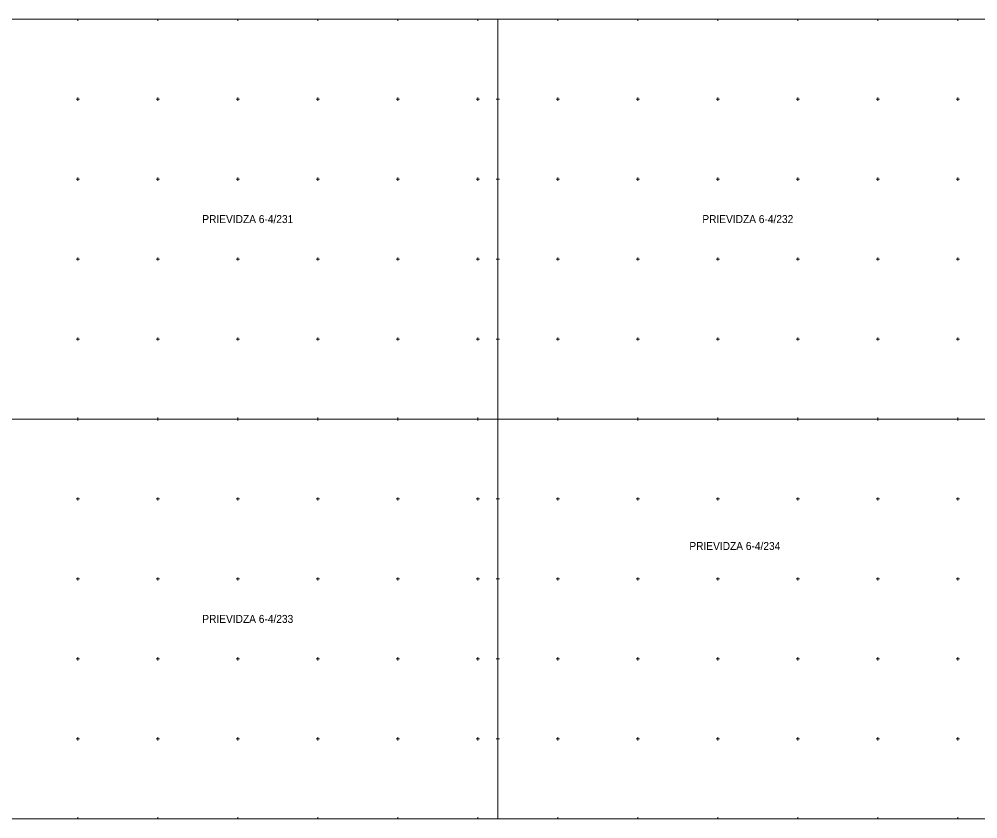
# Model space of a CAD drawing. Extents: x -46688 to -46438, y -123000 to -122825.
# Drawn here: x -46623.7 to -46563.8, y -122900 to -122850 of the extents above; entities that cross this region are included whole.
import ezdxf
from ezdxf.enums import TextEntityAlignment as Align

# ---------------------------------------------------------------- set-up
doc = ezdxf.new("R2010")
doc.units = 0
doc.header["$LTSCALE"] = 0.2
doc.layers.add('17', color=7, linetype='Continuous', lineweight=13)
doc.layers.add('18', color=7, linetype='Continuous', lineweight=13)
doc.layers.add('19', color=7, linetype='Continuous')

msp = doc.modelspace()

# ---------------------------------------------------------------- linework, layer by layer
at = {"layer": '17'}
for points in [[(-46593.75, -122850), (-46625, -122850), (-46625, -122875), (-46593.75, -122875)], [(-46562.5, -122850), (-46593.75, -122850), (-46593.75, -122875), (-46562.5, -122875)], [(-46593.75, -122875), (-46625, -122875), (-46625, -122900), (-46593.75, -122900)], [(-46562.5, -122875), (-46593.75, -122875), (-46593.75, -122900), (-46562.5, -122900)]]:
    msp.add_lwpolyline(points, close=True, dxfattribs=at)
at = {"layer": '18'}
for p, q in [((-46620, -122850), (-46620, -122850.1)), ((-46620, -122850), (-46620, -122850.1)), ((-46620, -122850), (-46620, -122850.1)), ((-46620, -122850), (-46620, -122850.1)), ((-46615, -122850), (-46615, -122850.1)), ((-46615, -122850), (-46615, -122850.1)), ((-46615, -122850), (-46615, -122850.1)), ((-46615, -122850), (-46615, -122850.1)), ((-46610, -122850), (-46610, -122850.1)), ((-46610, -122850), (-46610, -122850.1)), ((-46610, -122850), (-46610, -122850.1)), ((-46610, -122850), (-46610, -122850.1)), ((-46605, -122850), (-46605, -122850.1)), ((-46605, -122850), (-46605, -122850.1)), ((-46605, -122850), (-46605, -122850.1)), ((-46605, -122850), (-46605, -122850.1)), ((-46600, -122850), (-46600, -122850.1)), ((-46600, -122850), (-46600, -122850.1)), ((-46600, -122850), (-46600, -122850.1)), ((-46600, -122850), (-46600, -122850.1)), ((-46595, -122850), (-46595, -122850.1)), ((-46595, -122850), (-46595, -122850.1)), ((-46595, -122850), (-46595, -122850.1)), ((-46595, -122850), (-46595, -122850.1)), ((-46590, -122850), (-46590, -122850.1)), ((-46590, -122850), (-46590, -122850.1)), ((-46590, -122850), (-46590, -122850.1)), ((-46590, -122850), (-46590, -122850.1)), ((-46585, -122850), (-46585, -122850.1)), ((-46585, -122850), (-46585, -122850.1)), ((-46585, -122850), (-46585, -122850.1)), ((-46585, -122850), (-46585, -122850.1)), ((-46580, -122850), (-46580, -122850.1)), ((-46580, -122850), (-46580, -122850.1)), ((-46580, -122850), (-46580, -122850.1)), ((-46580, -122850), (-46580, -122850.1)), ((-46575, -122850), (-46575, -122850.1)), ((-46575, -122850), (-46575, -122850.1)), ((-46575, -122850), (-46575, -122850.1)), ((-46575, -122850), (-46575, -122850.1)), ((-46570, -122850), (-46570, -122850.1)), ((-46570, -122850), (-46570, -122850.1)), ((-46570, -122850), (-46570, -122850.1)), ((-46570, -122850), (-46570, -122850.1)), ((-46565, -122850), (-46565, -122850.1)), ((-46565, -122850), (-46565, -122850.1)), ((-46565, -122850), (-46565, -122850.1)), ((-46565, -122850), (-46565, -122850.1)), ((-46619.9, -122855), (-46620.1, -122855)), ((-46620, -122854.9), (-46620, -122855.1)), ((-46614.9, -122855), (-46615.1, -122855)), ((-46615, -122854.9), (-46615, -122855.1)), ((-46609.9, -122855), (-46610.1, -122855)), ((-46610, -122854.9), (-46610, -122855.1)), ((-46604.9, -122855), (-46605.1, -122855)), ((-46605, -122854.9), (-46605, -122855.1)), ((-46599.9, -122855), (-46600.1, -122855)), ((-46600, -122854.9), (-46600, -122855.1)), ((-46594.9, -122855), (-46595.1, -122855)), ((-46595, -122854.9), (-46595, -122855.1)), ((-46593.75, -122855), (-46593.85, -122855)), ((-46593.75, -122855), (-46593.65, -122855)), ((-46589.9, -122855), (-46590.1, -122855)), ((-46590, -122854.9), (-46590, -122855.1)), ((-46584.9, -122855), (-46585.1, -122855)), ((-46585, -122854.9), (-46585, -122855.1)), ((-46579.9, -122855), (-46580.1, -122855)), ((-46580, -122854.9), (-46580, -122855.1)), ((-46574.9, -122855), (-46575.1, -122855)), ((-46575, -122854.9), (-46575, -122855.1)), ((-46569.9, -122855), (-46570.1, -122855)), ((-46570, -122854.9), (-46570, -122855.1)), ((-46564.9, -122855), (-46565.1, -122855)), ((-46565, -122854.9), (-46565, -122855.1)), ((-46619.9, -122860), (-46620.1, -122860)), ((-46620, -122859.9), (-46620, -122860.1)), ((-46614.9, -122860), (-46615.1, -122860)), ((-46615, -122859.9), (-46615, -122860.1)), ((-46609.9, -122860), (-46610.1, -122860)), ((-46610, -122859.9), (-46610, -122860.1)), ((-46604.9, -122860), (-46605.1, -122860)), ((-46605, -122859.9), (-46605, -122860.1)), ((-46599.9, -122860), (-46600.1, -122860)), ((-46600, -122859.9), (-46600, -122860.1)), ((-46594.9, -122860), (-46595.1, -122860)), ((-46595, -122859.9), (-46595, -122860.1)), ((-46593.75, -122860), (-46593.85, -122860)), ((-46593.75, -122860), (-46593.65, -122860)), ((-46589.9, -122860), (-46590.1, -122860)), ((-46590, -122859.9), (-46590, -122860.1)), ((-46584.9, -122860), (-46585.1, -122860)), ((-46585, -122859.9), (-46585, -122860.1)), ((-46579.9, -122860), (-46580.1, -122860)), ((-46580, -122859.9), (-46580, -122860.1)), ((-46574.9, -122860), (-46575.1, -122860)), ((-46575, -122859.9), (-46575, -122860.1)), ((-46569.9, -122860), (-46570.1, -122860)), ((-46570, -122859.9), (-46570, -122860.1)), ((-46564.9, -122860), (-46565.1, -122860)), ((-46565, -122859.9), (-46565, -122860.1)), ((-46620, -122864.9), (-46620, -122865.1)), ((-46615, -122864.9), (-46615, -122865.1)), ((-46610, -122864.9), (-46610, -122865.1)), ((-46605, -122864.9), (-46605, -122865.1)), ((-46600, -122864.9), (-46600, -122865.1)), ((-46595, -122864.9), (-46595, -122865.1)), ((-46590, -122864.9), (-46590, -122865.1)), ((-46585, -122864.9), (-46585, -122865.1)), ((-46580, -122864.9), (-46580, -122865.1)), ((-46575, -122864.9), (-46575, -122865.1)), ((-46570, -122864.9), (-46570, -122865.1)), ((-46565, -122864.9), (-46565, -122865.1)), ((-46619.9, -122865), (-46620.1, -122865)), ((-46614.9, -122865), (-46615.1, -122865)), ((-46609.9, -122865), (-46610.1, -122865)), ((-46604.9, -122865), (-46605.1, -122865)), ((-46599.9, -122865), (-46600.1, -122865)), ((-46594.9, -122865), (-46595.1, -122865)), ((-46593.75, -122865), (-46593.85, -122865)), ((-46593.75, -122865), (-46593.65, -122865)), ((-46589.9, -122865), (-46590.1, -122865)), ((-46584.9, -122865), (-46585.1, -122865)), ((-46579.9, -122865), (-46580.1, -122865)), ((-46574.9, -122865), (-46575.1, -122865)), ((-46569.9, -122865), (-46570.1, -122865)), ((-46564.9, -122865), (-46565.1, -122865)), ((-46619.9, -122870), (-46620.1, -122870)), ((-46620, -122869.9), (-46620, -122870.1)), ((-46614.9, -122870), (-46615.1, -122870)), ((-46615, -122869.9), (-46615, -122870.1)), ((-46609.9, -122870), (-46610.1, -122870)), ((-46610, -122869.9), (-46610, -122870.1)), ((-46604.9, -122870), (-46605.1, -122870)), ((-46605, -122869.9), (-46605, -122870.1)), ((-46599.9, -122870), (-46600.1, -122870)), ((-46600, -122869.9), (-46600, -122870.1)), ((-46594.9, -122870), (-46595.1, -122870)), ((-46595, -122869.9), (-46595, -122870.1)), ((-46593.75, -122870), (-46593.85, -122870)), ((-46593.75, -122870), (-46593.65, -122870)), ((-46589.9, -122870), (-46590.1, -122870)), ((-46590, -122869.9), (-46590, -122870.1)), ((-46584.9, -122870), (-46585.1, -122870)), ((-46585, -122869.9), (-46585, -122870.1)), ((-46579.9, -122870), (-46580.1, -122870)), ((-46580, -122869.9), (-46580, -122870.1)), ((-46574.9, -122870), (-46575.1, -122870)), ((-46575, -122869.9), (-46575, -122870.1)), ((-46569.9, -122870), (-46570.1, -122870)), ((-46570, -122869.9), (-46570, -122870.1)), ((-46564.9, -122870), (-46565.1, -122870)), ((-46565, -122869.9), (-46565, -122870.1)), ((-46620, -122875), (-46620, -122874.9)), ((-46620, -122875), (-46620, -122874.9)), ((-46620, -122875), (-46620, -122874.9)), ((-46620, -122875), (-46620, -122874.9)), ((-46620, -122875), (-46620, -122875.1)), ((-46620, -122875), (-46620, -122875.1)), ((-46620, -122875), (-46620, -122875.1)), ((-46620, -122875), (-46620, -122875.1)), ((-46615, -122875), (-46615, -122874.9)), ((-46615, -122875), (-46615, -122874.9)), ((-46615, -122875), (-46615, -122874.9)), ((-46615, -122875), (-46615, -122874.9)), ((-46615, -122875), (-46615, -122875.1)), ((-46615, -122875), (-46615, -122875.1)), ((-46615, -122875), (-46615, -122875.1)), ((-46615, -122875), (-46615, -122875.1)), ((-46610, -122875), (-46610, -122874.9)), ((-46610, -122875), (-46610, -122874.9)), ((-46610, -122875), (-46610, -122874.9)), ((-46610, -122875), (-46610, -122874.9)), ((-46610, -122875), (-46610, -122875.1)), ((-46610, -122875), (-46610, -122875.1)), ((-46610, -122875), (-46610, -122875.1)), ((-46610, -122875), (-46610, -122875.1)), ((-46605, -122875), (-46605, -122874.9)), ((-46605, -122875), (-46605, -122874.9)), ((-46605, -122875), (-46605, -122874.9)), ((-46605, -122875), (-46605, -122874.9)), ((-46605, -122875), (-46605, -122875.1)), ((-46605, -122875), (-46605, -122875.1)), ((-46605, -122875), (-46605, -122875.1)), ((-46605, -122875), (-46605, -122875.1)), ((-46600, -122875), (-46600, -122874.9)), ((-46600, -122875), (-46600, -122874.9)), ((-46600, -122875), (-46600, -122874.9)), ((-46600, -122875), (-46600, -122874.9)), ((-46600, -122875), (-46600, -122875.1)), ((-46600, -122875), (-46600, -122875.1)), ((-46600, -122875), (-46600, -122875.1)), ((-46600, -122875), (-46600, -122875.1)), ((-46595, -122875), (-46595, -122874.9)), ((-46595, -122875), (-46595, -122874.9)), ((-46595, -122875), (-46595, -122874.9)), ((-46595, -122875), (-46595, -122874.9)), ((-46595, -122875), (-46595, -122875.1)), ((-46595, -122875), (-46595, -122875.1)), ((-46595, -122875), (-46595, -122875.1)), ((-46595, -122875), (-46595, -122875.1)), ((-46590, -122875), (-46590, -122874.9)), ((-46590, -122875), (-46590, -122874.9)), ((-46590, -122875), (-46590, -122874.9)), ((-46590, -122875), (-46590, -122874.9)), ((-46590, -122875), (-46590, -122875.1)), ((-46590, -122875), (-46590, -122875.1)), ((-46590, -122875), (-46590, -122875.1)), ((-46590, -122875), (-46590, -122875.1)), ((-46585, -122875), (-46585, -122874.9)), ((-46585, -122875), (-46585, -122874.9)), ((-46585, -122875), (-46585, -122874.9)), ((-46585, -122875), (-46585, -122874.9)), ((-46585, -122875), (-46585, -122875.1)), ((-46585, -122875), (-46585, -122875.1)), ((-46585, -122875), (-46585, -122875.1)), ((-46585, -122875), (-46585, -122875.1)), ((-46580, -122875), (-46580, -122874.9)), ((-46580, -122875), (-46580, -122874.9)), ((-46580, -122875), (-46580, -122874.9)), ((-46580, -122875), (-46580, -122874.9)), ((-46580, -122875), (-46580, -122875.1)), ((-46580, -122875), (-46580, -122875.1)), ((-46580, -122875), (-46580, -122875.1)), ((-46580, -122875), (-46580, -122875.1)), ((-46575, -122875), (-46575, -122874.9)), ((-46575, -122875), (-46575, -122874.9)), ((-46575, -122875), (-46575, -122874.9)), ((-46575, -122875), (-46575, -122874.9)), ((-46575, -122875), (-46575, -122875.1)), ((-46575, -122875), (-46575, -122875.1)), ((-46575, -122875), (-46575, -122875.1)), ((-46575, -122875), (-46575, -122875.1)), ((-46570, -122875), (-46570, -122874.9)), ((-46570, -122875), (-46570, -122874.9)), ((-46570, -122875), (-46570, -122874.9)), ((-46570, -122875), (-46570, -122874.9)), ((-46570, -122875), (-46570, -122875.1)), ((-46570, -122875), (-46570, -122875.1)), ((-46570, -122875), (-46570, -122875.1)), ((-46570, -122875), (-46570, -122875.1)), ((-46565, -122875), (-46565, -122874.9)), ((-46565, -122875), (-46565, -122874.9)), ((-46565, -122875), (-46565, -122874.9)), ((-46565, -122875), (-46565, -122874.9)), ((-46565, -122875), (-46565, -122875.1)), ((-46565, -122875), (-46565, -122875.1)), ((-46565, -122875), (-46565, -122875.1)), ((-46565, -122875), (-46565, -122875.1)), ((-46620, -122879.9), (-46620, -122880.1)), ((-46615, -122879.9), (-46615, -122880.1)), ((-46610, -122879.9), (-46610, -122880.1)), ((-46605, -122879.9), (-46605, -122880.1)), ((-46600, -122879.9), (-46600, -122880.1)), ((-46595, -122879.9), (-46595, -122880.1)), ((-46590, -122879.9), (-46590, -122880.1)), ((-46585, -122879.9), (-46585, -122880.1)), ((-46580, -122879.9), (-46580, -122880.1)), ((-46575, -122879.9), (-46575, -122880.1)), ((-46570, -122879.9), (-46570, -122880.1)), ((-46565, -122879.9), (-46565, -122880.1)), ((-46619.9, -122880), (-46620.1, -122880)), ((-46614.9, -122880), (-46615.1, -122880)), ((-46609.9, -122880), (-46610.1, -122880)), ((-46604.9, -122880), (-46605.1, -122880)), ((-46599.9, -122880), (-46600.1, -122880)), ((-46594.9, -122880), (-46595.1, -122880)), ((-46593.75, -122880), (-46593.85, -122880)), ((-46593.75, -122880), (-46593.65, -122880)), ((-46589.9, -122880), (-46590.1, -122880)), ((-46584.9, -122880), (-46585.1, -122880)), ((-46579.9, -122880), (-46580.1, -122880)), ((-46574.9, -122880), (-46575.1, -122880)), ((-46569.9, -122880), (-46570.1, -122880)), ((-46564.9, -122880), (-46565.1, -122880)), ((-46619.9, -122885), (-46620.1, -122885)), ((-46620, -122884.9), (-46620, -122885.1)), ((-46614.9, -122885), (-46615.1, -122885)), ((-46615, -122884.9), (-46615, -122885.1)), ((-46609.9, -122885), (-46610.1, -122885)), ((-46610, -122884.9), (-46610, -122885.1)), ((-46604.9, -122885), (-46605.1, -122885)), ((-46605, -122884.9), (-46605, -122885.1)), ((-46599.9, -122885), (-46600.1, -122885)), ((-46600, -122884.9), (-46600, -122885.1)), ((-46594.9, -122885), (-46595.1, -122885)), ((-46595, -122884.9), (-46595, -122885.1)), ((-46593.75, -122885), (-46593.85, -122885)), ((-46593.75, -122885), (-46593.65, -122885)), ((-46589.9, -122885), (-46590.1, -122885)), ((-46590, -122884.9), (-46590, -122885.1)), ((-46584.9, -122885), (-46585.1, -122885)), ((-46585, -122884.9), (-46585, -122885.1)), ((-46579.9, -122885), (-46580.1, -122885)), ((-46580, -122884.9), (-46580, -122885.1)), ((-46574.9, -122885), (-46575.1, -122885)), ((-46575, -122884.9), (-46575, -122885.1)), ((-46569.9, -122885), (-46570.1, -122885)), ((-46570, -122884.9), (-46570, -122885.1)), ((-46564.9, -122885), (-46565.1, -122885)), ((-46565, -122884.9), (-46565, -122885.1)), ((-46619.9, -122890), (-46620.1, -122890)), ((-46620, -122889.9), (-46620, -122890.1)), ((-46614.9, -122890), (-46615.1, -122890)), ((-46615, -122889.9), (-46615, -122890.1)), ((-46609.9, -122890), (-46610.1, -122890)), ((-46610, -122889.9), (-46610, -122890.1)), ((-46604.9, -122890), (-46605.1, -122890)), ((-46605, -122889.9), (-46605, -122890.1)), ((-46599.9, -122890), (-46600.1, -122890)), ((-46600, -122889.9), (-46600, -122890.1)), ((-46594.9, -122890), (-46595.1, -122890)), ((-46595, -122889.9), (-46595, -122890.1)), ((-46593.75, -122890), (-46593.85, -122890)), ((-46593.75, -122890), (-46593.65, -122890)), ((-46589.9, -122890), (-46590.1, -122890)), ((-46590, -122889.9), (-46590, -122890.1)), ((-46584.9, -122890), (-46585.1, -122890)), ((-46585, -122889.9), (-46585, -122890.1)), ((-46579.9, -122890), (-46580.1, -122890)), ((-46580, -122889.9), (-46580, -122890.1)), ((-46574.9, -122890), (-46575.1, -122890)), ((-46575, -122889.9), (-46575, -122890.1)), ((-46569.9, -122890), (-46570.1, -122890)), ((-46570, -122889.9), (-46570, -122890.1)), ((-46564.9, -122890), (-46565.1, -122890)), ((-46565, -122889.9), (-46565, -122890.1)), ((-46620, -122894.9), (-46620, -122895.1)), ((-46615, -122894.9), (-46615, -122895.1)), ((-46610, -122894.9), (-46610, -122895.1)), ((-46605, -122894.9), (-46605, -122895.1)), ((-46600, -122894.9), (-46600, -122895.1)), ((-46595, -122894.9), (-46595, -122895.1)), ((-46590, -122894.9), (-46590, -122895.1)), ((-46585, -122894.9), (-46585, -122895.1)), ((-46580, -122894.9), (-46580, -122895.1)), ((-46575, -122894.9), (-46575, -122895.1)), ((-46570, -122894.9), (-46570, -122895.1)), ((-46565, -122894.9), (-46565, -122895.1)), ((-46619.9, -122895), (-46620.1, -122895)), ((-46614.9, -122895), (-46615.1, -122895)), ((-46609.9, -122895), (-46610.1, -122895)), ((-46604.9, -122895), (-46605.1, -122895)), ((-46599.9, -122895), (-46600.1, -122895)), ((-46594.9, -122895), (-46595.1, -122895)), ((-46593.75, -122895), (-46593.85, -122895)), ((-46593.75, -122895), (-46593.65, -122895)), ((-46589.9, -122895), (-46590.1, -122895)), ((-46584.9, -122895), (-46585.1, -122895)), ((-46579.9, -122895), (-46580.1, -122895)), ((-46574.9, -122895), (-46575.1, -122895)), ((-46569.9, -122895), (-46570.1, -122895)), ((-46564.9, -122895), (-46565.1, -122895)), ((-46620, -122900), (-46620, -122899.9)), ((-46620, -122900), (-46620, -122899.9)), ((-46620, -122900), (-46620, -122899.9)), ((-46620, -122900), (-46620, -122899.9)), ((-46615, -122900), (-46615, -122899.9)), ((-46615, -122900), (-46615, -122899.9)), ((-46615, -122900), (-46615, -122899.9)), ((-46615, -122900), (-46615, -122899.9)), ((-46610, -122900), (-46610, -122899.9)), ((-46610, -122900), (-46610, -122899.9)), ((-46610, -122900), (-46610, -122899.9)), ((-46610, -122900), (-46610, -122899.9)), ((-46605, -122900), (-46605, -122899.9)), ((-46605, -122900), (-46605, -122899.9)), ((-46605, -122900), (-46605, -122899.9)), ((-46605, -122900), (-46605, -122899.9)), ((-46600, -122900), (-46600, -122899.9)), ((-46600, -122900), (-46600, -122899.9)), ((-46600, -122900), (-46600, -122899.9)), ((-46600, -122900), (-46600, -122899.9)), ((-46595, -122900), (-46595, -122899.9)), ((-46595, -122900), (-46595, -122899.9)), ((-46595, -122900), (-46595, -122899.9)), ((-46595, -122900), (-46595, -122899.9)), ((-46590, -122900), (-46590, -122899.9)), ((-46590, -122900), (-46590, -122899.9)), ((-46590, -122900), (-46590, -122899.9)), ((-46590, -122900), (-46590, -122899.9)), ((-46585, -122900), (-46585, -122899.9)), ((-46585, -122900), (-46585, -122899.9)), ((-46585, -122900), (-46585, -122899.9)), ((-46585, -122900), (-46585, -122899.9)), ((-46580, -122900), (-46580, -122899.9)), ((-46580, -122900), (-46580, -122899.9)), ((-46580, -122900), (-46580, -122899.9)), ((-46580, -122900), (-46580, -122899.9)), ((-46575, -122900), (-46575, -122899.9)), ((-46575, -122900), (-46575, -122899.9)), ((-46575, -122900), (-46575, -122899.9)), ((-46575, -122900), (-46575, -122899.9)), ((-46570, -122900), (-46570, -122899.9)), ((-46570, -122900), (-46570, -122899.9)), ((-46570, -122900), (-46570, -122899.9)), ((-46570, -122900), (-46570, -122899.9)), ((-46565, -122900), (-46565, -122899.9)), ((-46565, -122900), (-46565, -122899.9)), ((-46565, -122900), (-46565, -122899.9)), ((-46565, -122900), (-46565, -122899.9))]:
    msp.add_line(p, q, dxfattribs=at)

# ---------------------------------------------------------------- texts
at = {"layer": '19', "width": 0.95}
for s, p in [('PRIEVIDZA 6-4/231', (-46609.375, -122862.75)), ('PRIEVIDZA 6-4/232', (-46578.125, -122862.75)), ('PRIEVIDZA 6-4/234', (-46578.936, -122883.191)), ('PRIEVIDZA 6-4/233', (-46609.375, -122887.75))]:
    msp.add_text(s, height=0.5, dxfattribs=at).set_placement(p, align=Align.CENTER)

doc.saveas('drawing.dxf')
